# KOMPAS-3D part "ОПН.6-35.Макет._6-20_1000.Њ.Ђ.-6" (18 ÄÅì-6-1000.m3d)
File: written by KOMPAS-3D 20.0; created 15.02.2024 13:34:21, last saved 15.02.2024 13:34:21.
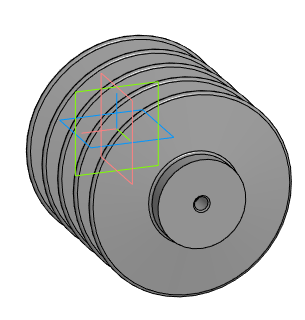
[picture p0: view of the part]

Document properties: Полное имя файла: C:\Users\drmla\OneDrive\Рабочий стол\ОПН\Модели\3 класс\ОПН.6-35.Макет._6-20_1000.Њ.Ђ.-6.m3d

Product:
- Part/product: ОПН.6-35.Макет._6-20_1000.Њ.Ђ.-6

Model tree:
1. Операция без истории:1  (labels: ОПН.6-35.Макет._6-20_1000.Њ.Ђ.-6)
